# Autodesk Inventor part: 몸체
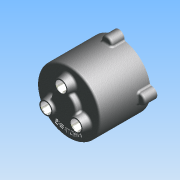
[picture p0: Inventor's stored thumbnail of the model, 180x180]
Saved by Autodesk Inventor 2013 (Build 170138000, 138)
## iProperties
Company: 한국ATC센터
Created: 2014-07
Part Number: 몸체
Document SubType Name: 모델링
Designer: KYOUNG IL JANG
Material: 알루미늄 6061
Mass: 475.555 g
Surface Area: 687.66 cm^2
Volume: 175.481 cm^3
Density: 2.71 g/cm^3
변환 표준: STEP AP214IS
파일 이름: C:\Users\SeoGD\Desktop\?쒗뿕\紐몄껜.stp
전처리기: Build: 253, Release: 2010 SP1 - Date: Wed 07/29/2009
전송 단위: 밀리미터
불확실성: 0.01
Author: KYOUNG IL JANG
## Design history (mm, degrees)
sketch "스케치2"
  geometry: C1 r 50 at (0, 0); 1 further point
  constraints: 1 centre point, 1 coincident
  dimensions: "d9" = 100 diameter of C1
extrude "돌출2" new body sketch "스케치2" distance "d10" = 80; taper "d11" = 0 deg
feature "쉘1" dims "d12" = 5
sketch "스케치3" dims "d13" = 55
  geometry: C1 r 7.5 at (0, 27.5); C2 r 12.5 at (0, 27.5); 2 further points
  constraints: 2 centre point, 2 coincident, 2 vertical alignment, 2 other
  dimensions: "d14" = 15 diameter of C1; "d15" = 25 diameter of C2
extrude "돌출3" join sketch "스케치3" distance "d16" = 12; taper "d17" = -10 deg
hole "구멍2" diameter "d20" = 15; stored, may be unused: countersink angle "d24" = 90 deg, drill point angle "d26" = 118 deg; dims "d18" = 10, "d19" = 10, "d21" = 6, "d22" = 4, "d23" = 2, "d25" = 15
chamfer "모따기1" distance "d27" = 1; stored, may be unused: second distance "d28" = 2, angle "d29" = 45 deg
revolve "회전1" stored, may be unused: angle "d38" = 90 deg
hole "구멍3" diameter "d41" = 15; stored, may be unused: countersink angle "d45" = 90 deg, drill point angle "d47" = 0 deg; dims "d39" = 10, "d40" = 10, "d42" = 6, "d43" = 22, "d44" = 13, "d46" = 15
chamfer "모따기2" distance "d48" = 1; stored, may be unused: second distance "d49" = 2, angle "d50" = 45 deg
fillet "모깎기1" dims "d52" = 3
fillet "모깎기2" dims "d53" = 3, "d72" = 0.2
sketch "스케치5"
  geometry: A1 r 50 centre (0, 0) between (50, 0) and (-8.074, 49.344) reference; A2 r 8.5 centre (0, 52) between (8.074, 49.344) and (-8.074, 49.344); 1 further point
  constraints: 5 point on circle, 1 centre point, 1 horizontal alignment
  dimensions: "d54" = 90 deg dimension on point (0, 0) A2.centre A1.start; "d55" = 52 distance of A2.centre point (0, 0); "d56" = 17 diameter of A2
extrude "돌출4" join sketch "스케치5" distance "d57" = 20; taper "d58" = 0 deg
fillet "모깎기3" dims "d59" = 3
hole "구멍4" diameter "d62" = 4.134; stored, may be unused: countersink angle "d66" = 90 deg, drill point angle "d68" = 118 deg; dims "d60" = 10, "d61" = 10, "d63" = 12, "d64" = 22, "d65" = 13, "d67" = 15
feature "엠보싱1" dims "d74" = 1, "d75" = 0
node "솔리드1"
node "솔리드 본체"
node "곡면 본체"
pattern_circular "원형 패턴1" dims "d31" = 360 deg
pattern_circular "원형 패턴2" dims "d70" = 360 deg
node "솔리드2"
sketch "스케치4"
  geometry: L1 (0, 0)-(0, 88); L2 (0, 70)-(13.16, 70); L3 (-45, 75)-(45, 75) reference; L4 (-50, 80)-(50, 80) reference; L5 (13.16, 70)-(14.5, 75); L6 (20, 80)-(20, 88); L7 (20, 88)-(0, 88); L8 (20, 80)-(14.5, 75)
  constraints: 12 end point, 3 point on line, 2 perpendicular, 1 vertical
  dimensions: "d34" = 40 diameter of L6 L1; "d35" = 105 deg angle of L5 L3; "d36" = 5 distance between parallel lines of L2 L3; "d37" = 8 distance between parallel lines of L7 L4; "d51" = 29 diameter of L5.end L1
sketch "스케치6"
  geometry: C1 r 47 at (0, 0) reference; C2 r 42.5 at (0, 0); 1 further point
  constraints: 1 centre point, 1 coincident, 1 other
  dimensions: "d73" = 85 diameter of C2
